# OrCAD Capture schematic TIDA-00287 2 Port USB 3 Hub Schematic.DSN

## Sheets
1 PAGE1_BLOCK_DIAGRAM: title: BLOCK DIAGRAM; rev: A
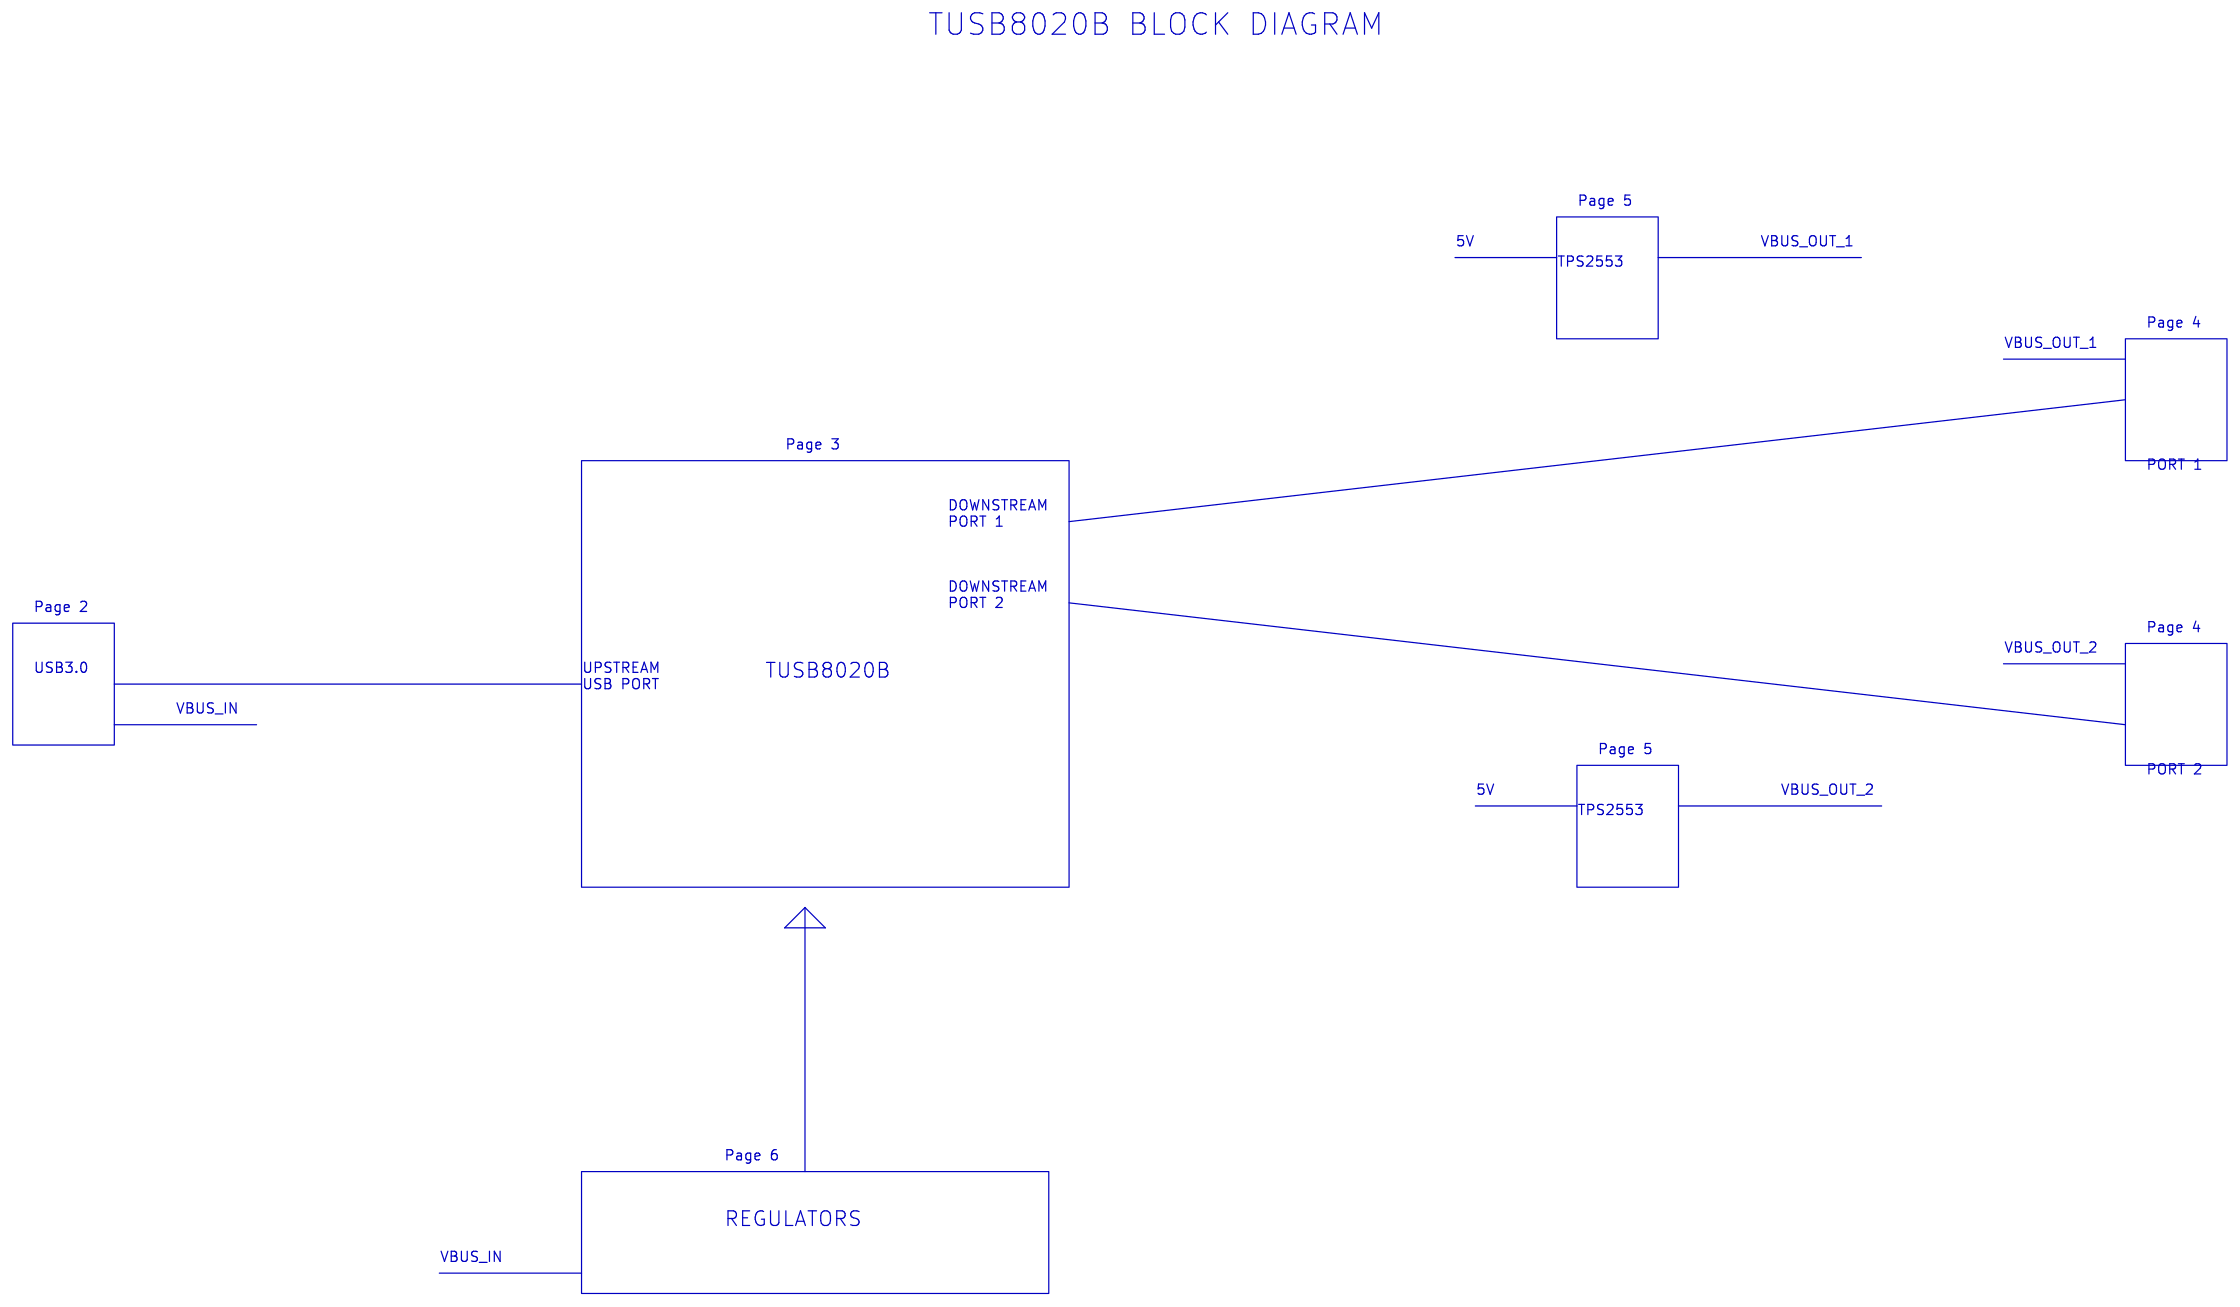
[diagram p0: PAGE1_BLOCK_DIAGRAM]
2 PAGE2_USB3_UPSTREAM_CONNECTOR: size B; title: USB 3.0 UPSTREAM CONNECTOR
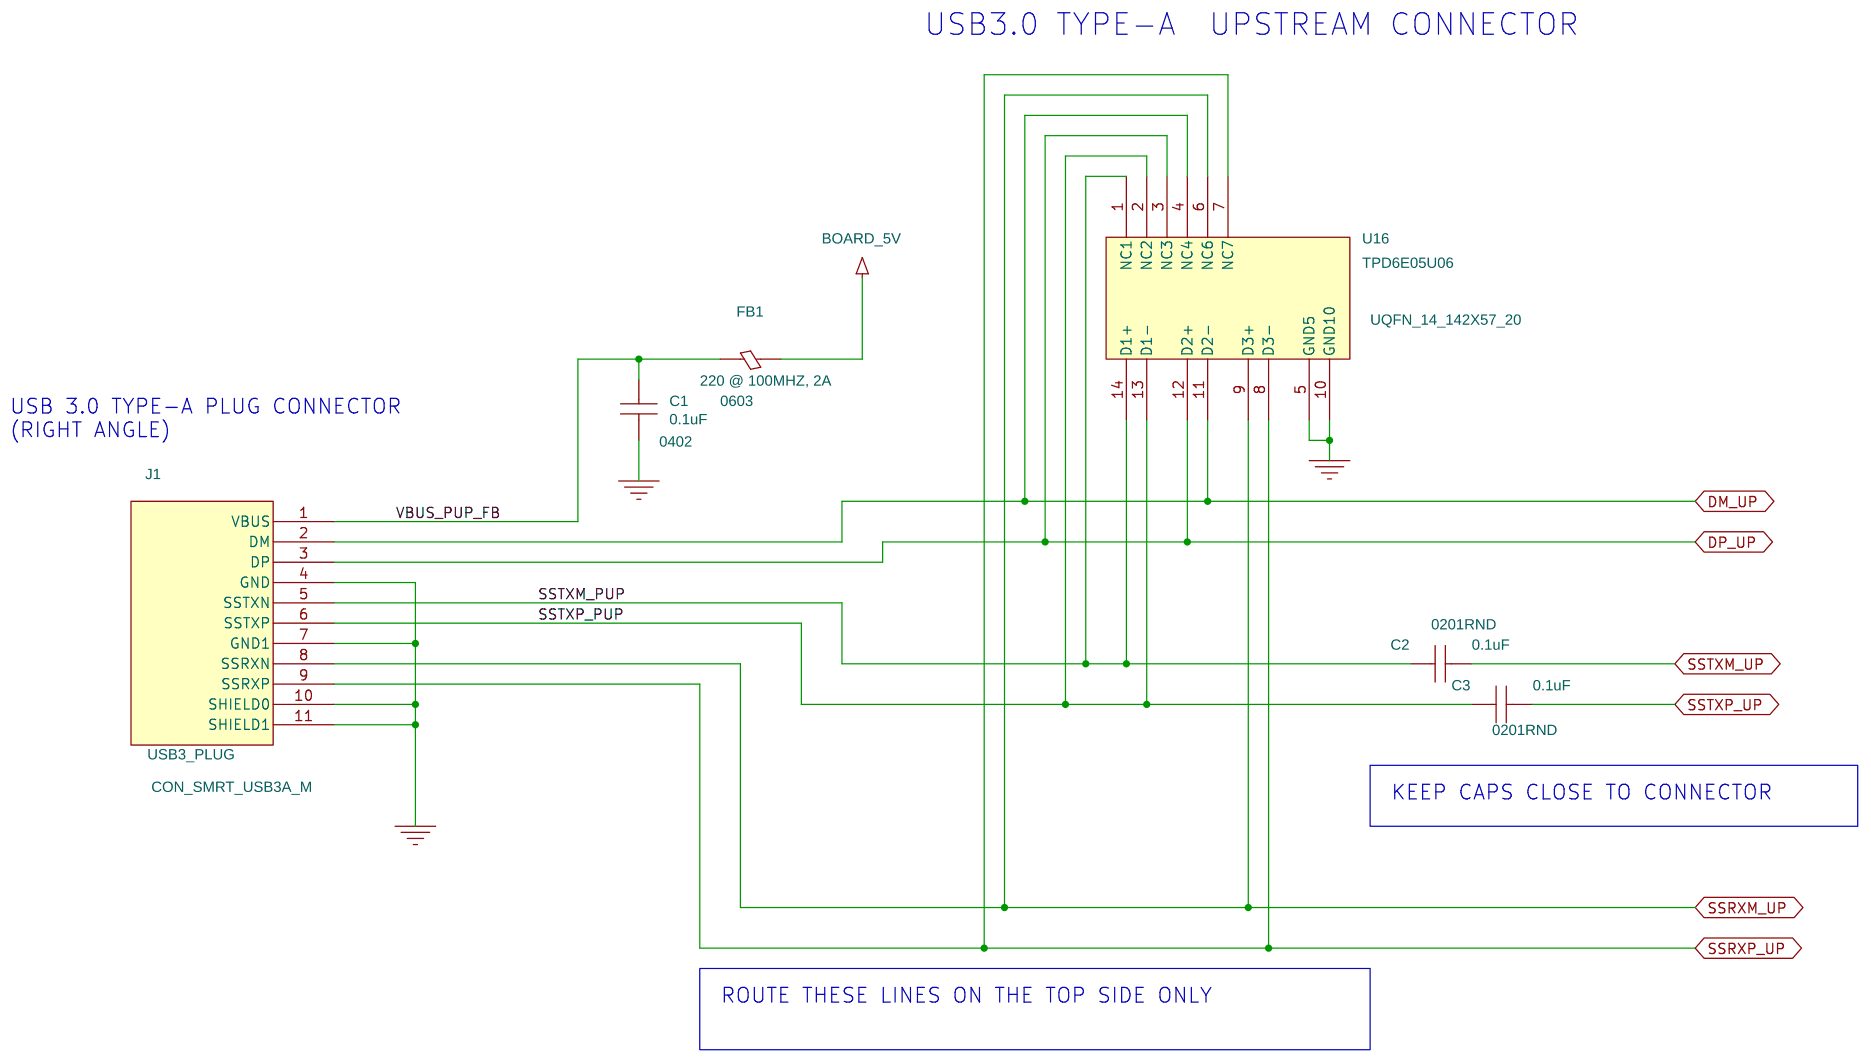
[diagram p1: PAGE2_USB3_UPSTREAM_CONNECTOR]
3 PAGE3_TUSB8020B: size B; title: TUSB8020B
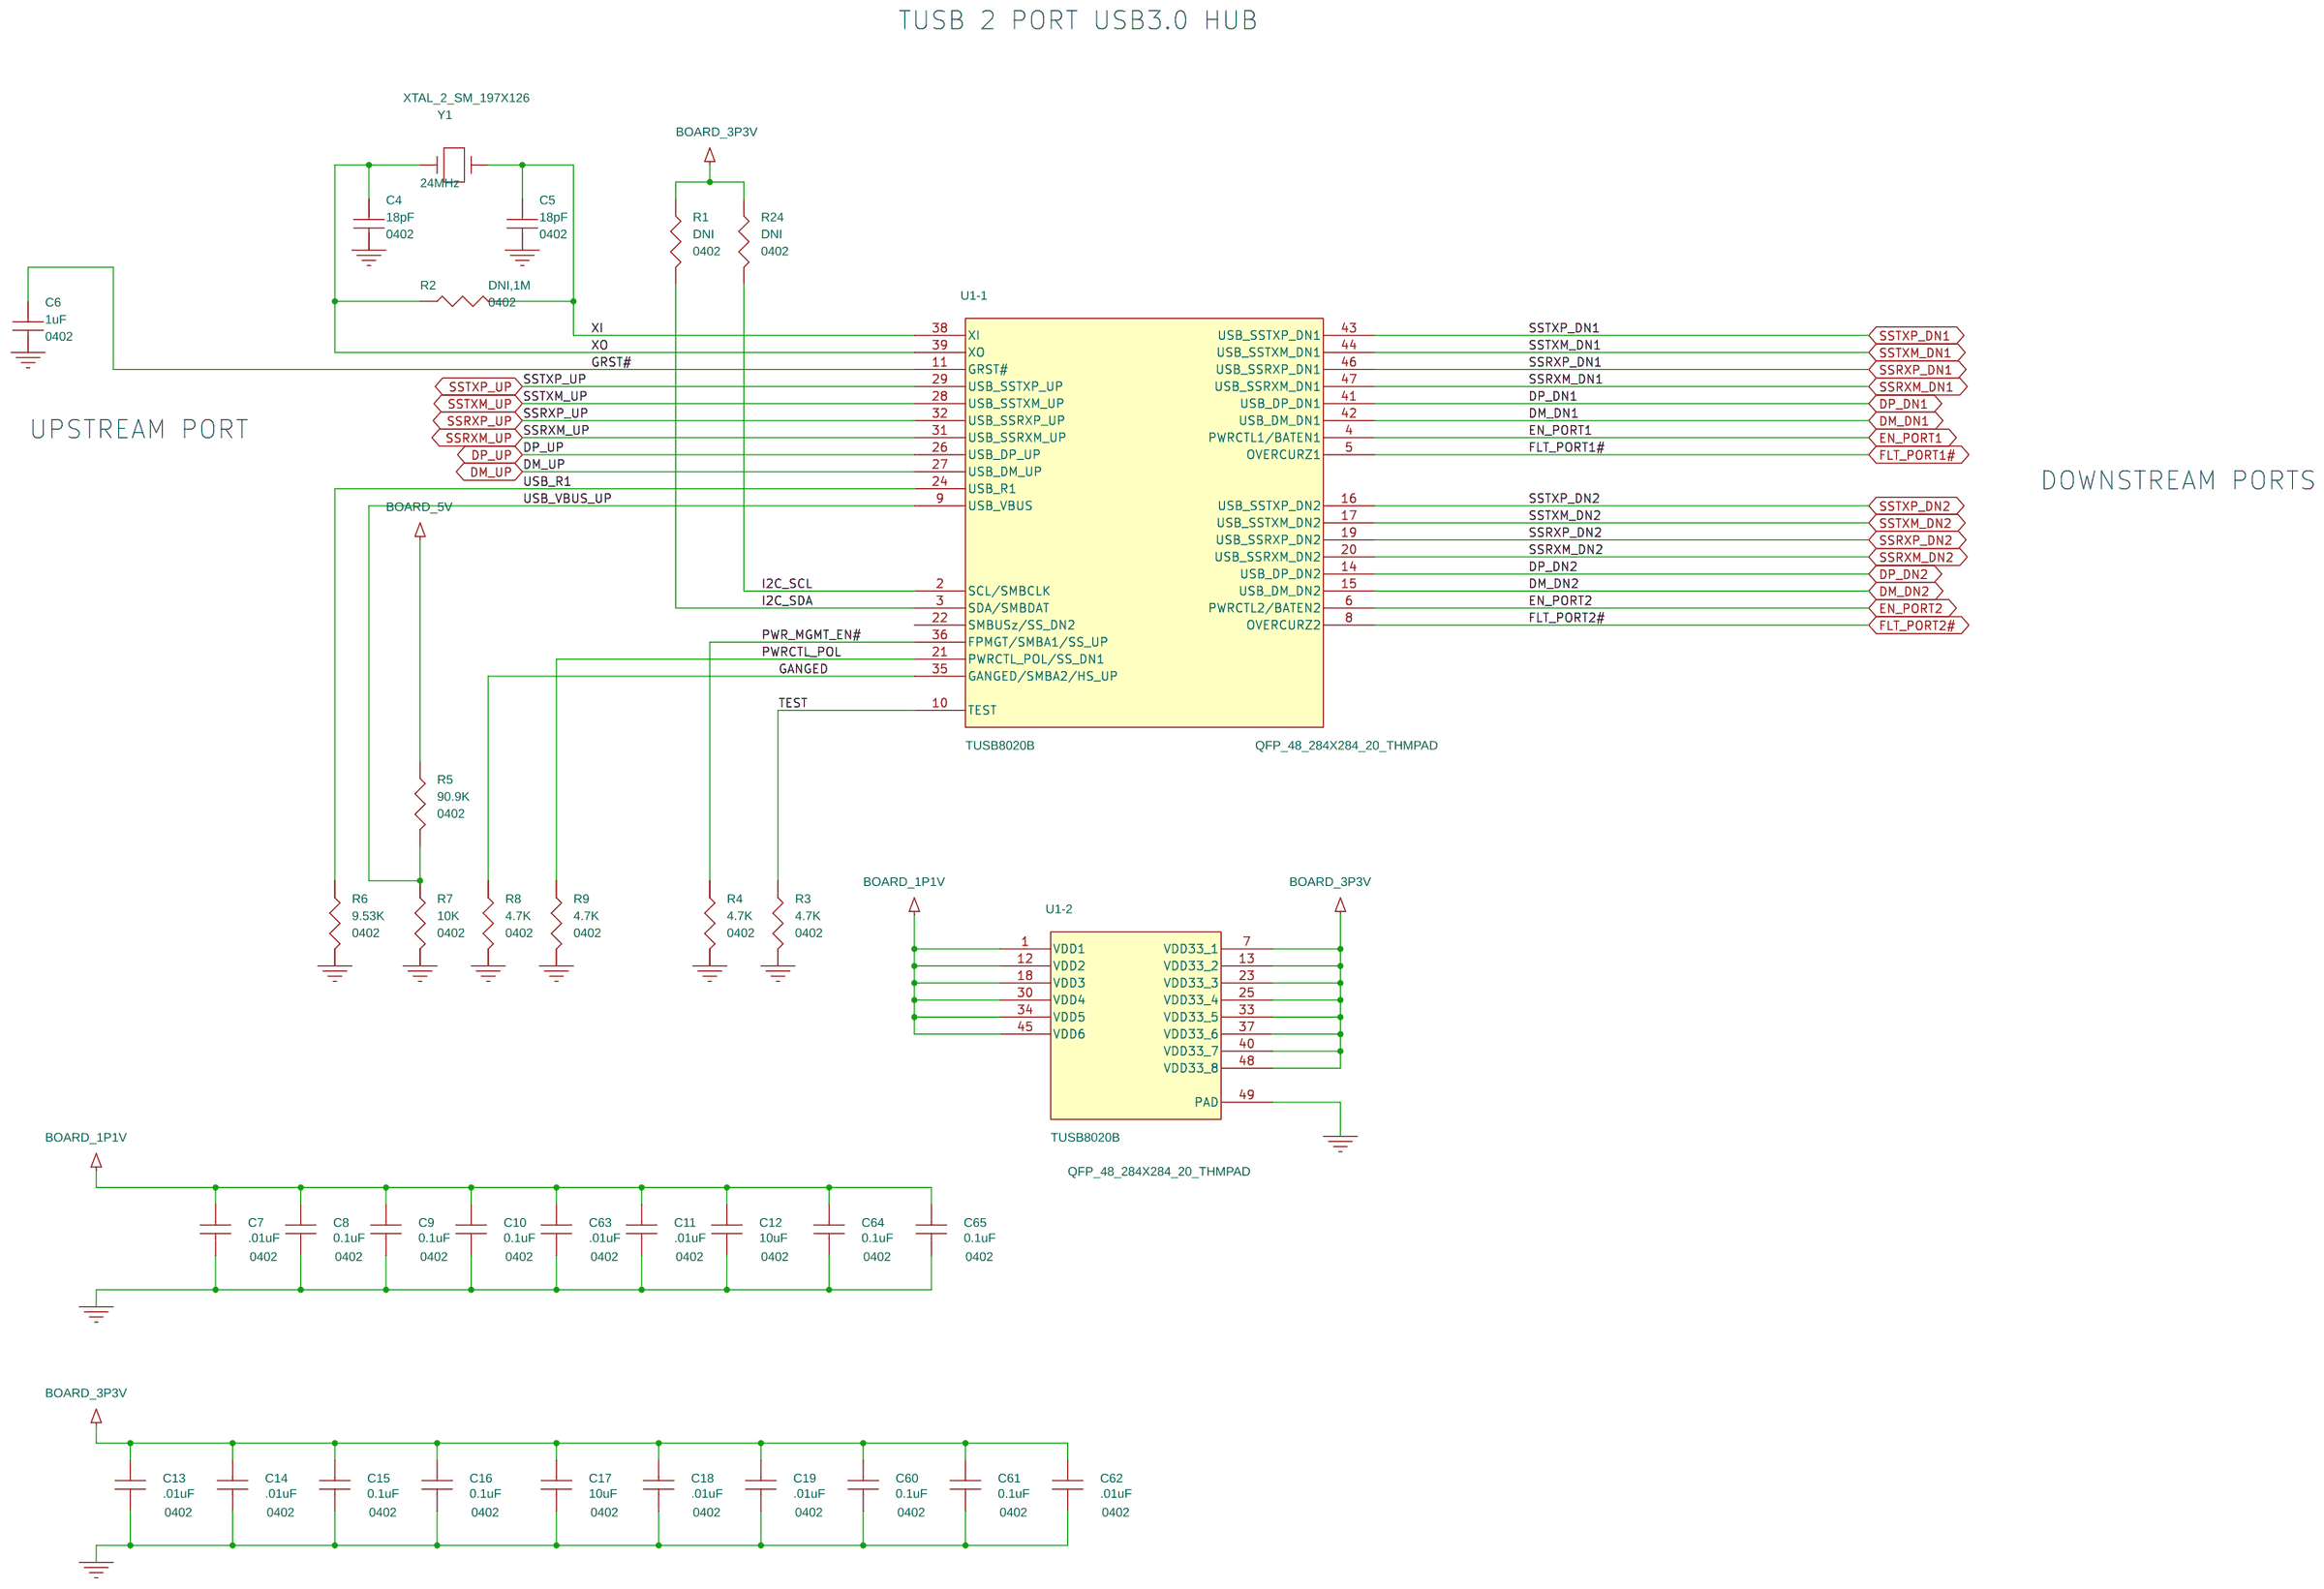
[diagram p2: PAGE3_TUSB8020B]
4 PAGE4_USB_DOWNSTREAM_PORTS_1_2: size B; title: USB DOWNSTREAM PORTS 1 AND 2; rev: B
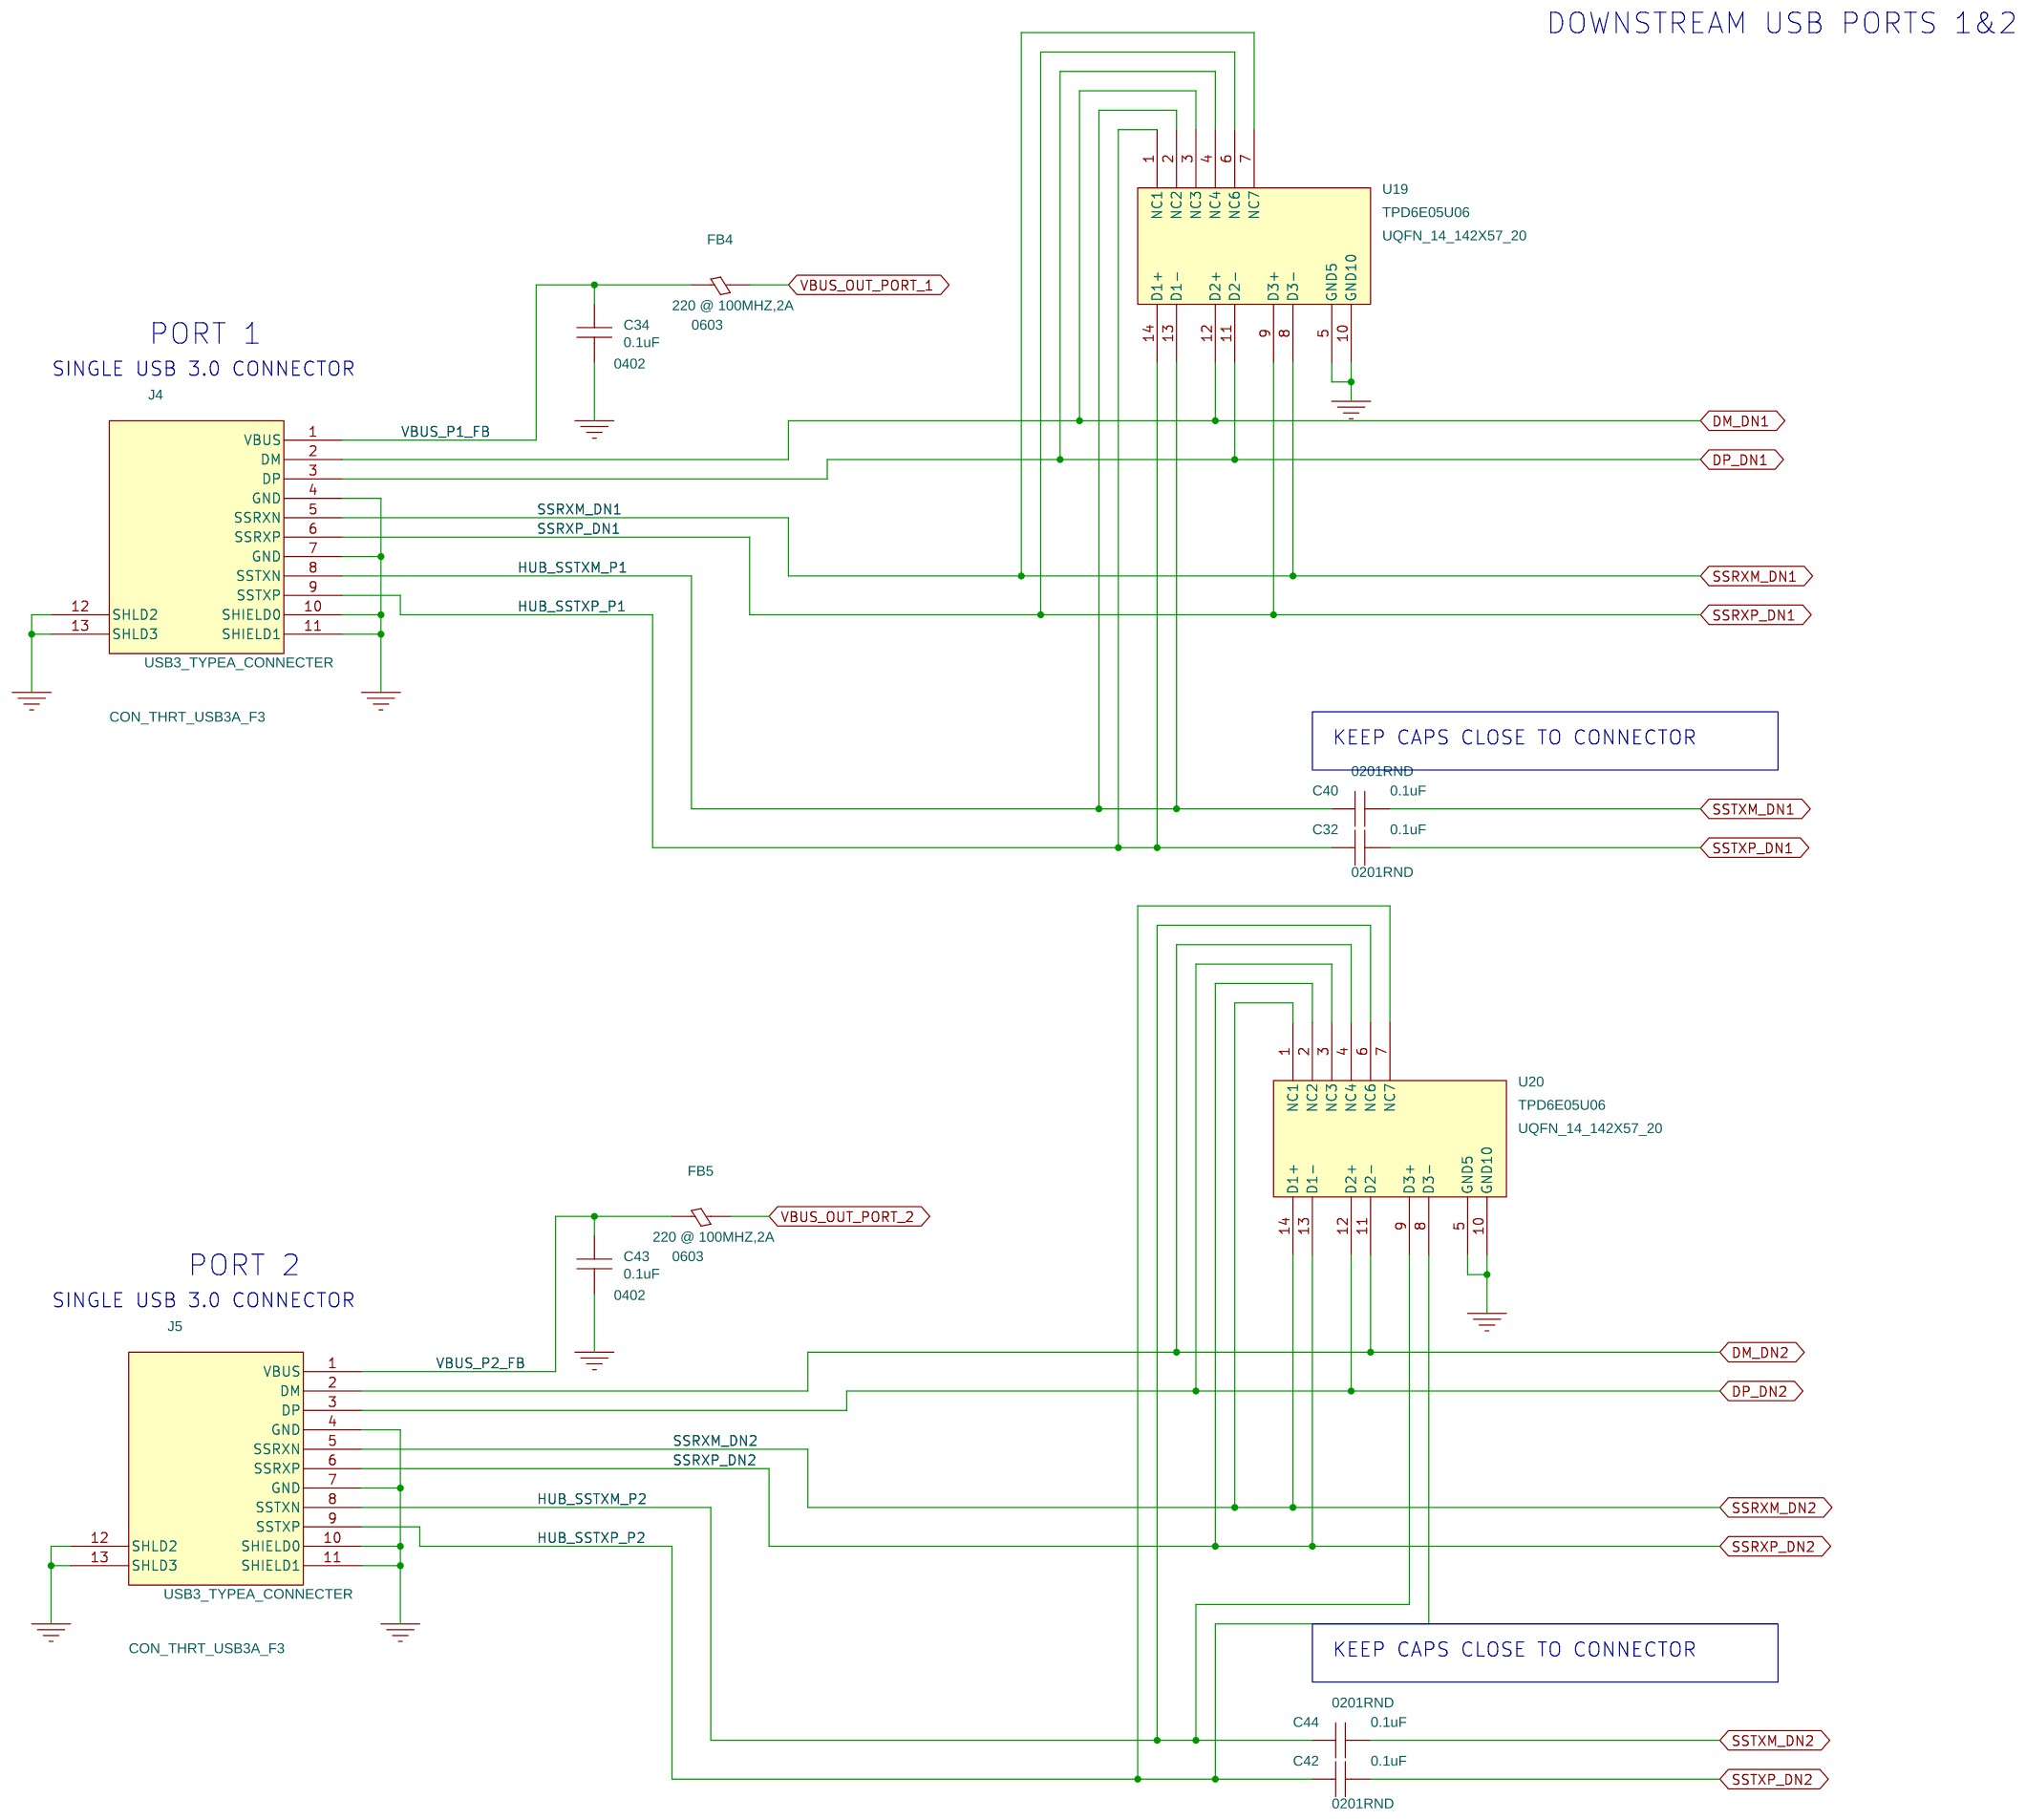
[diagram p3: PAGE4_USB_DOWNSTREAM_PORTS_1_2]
5 PAGE5_USB_POWER: size B; title: USB POWER
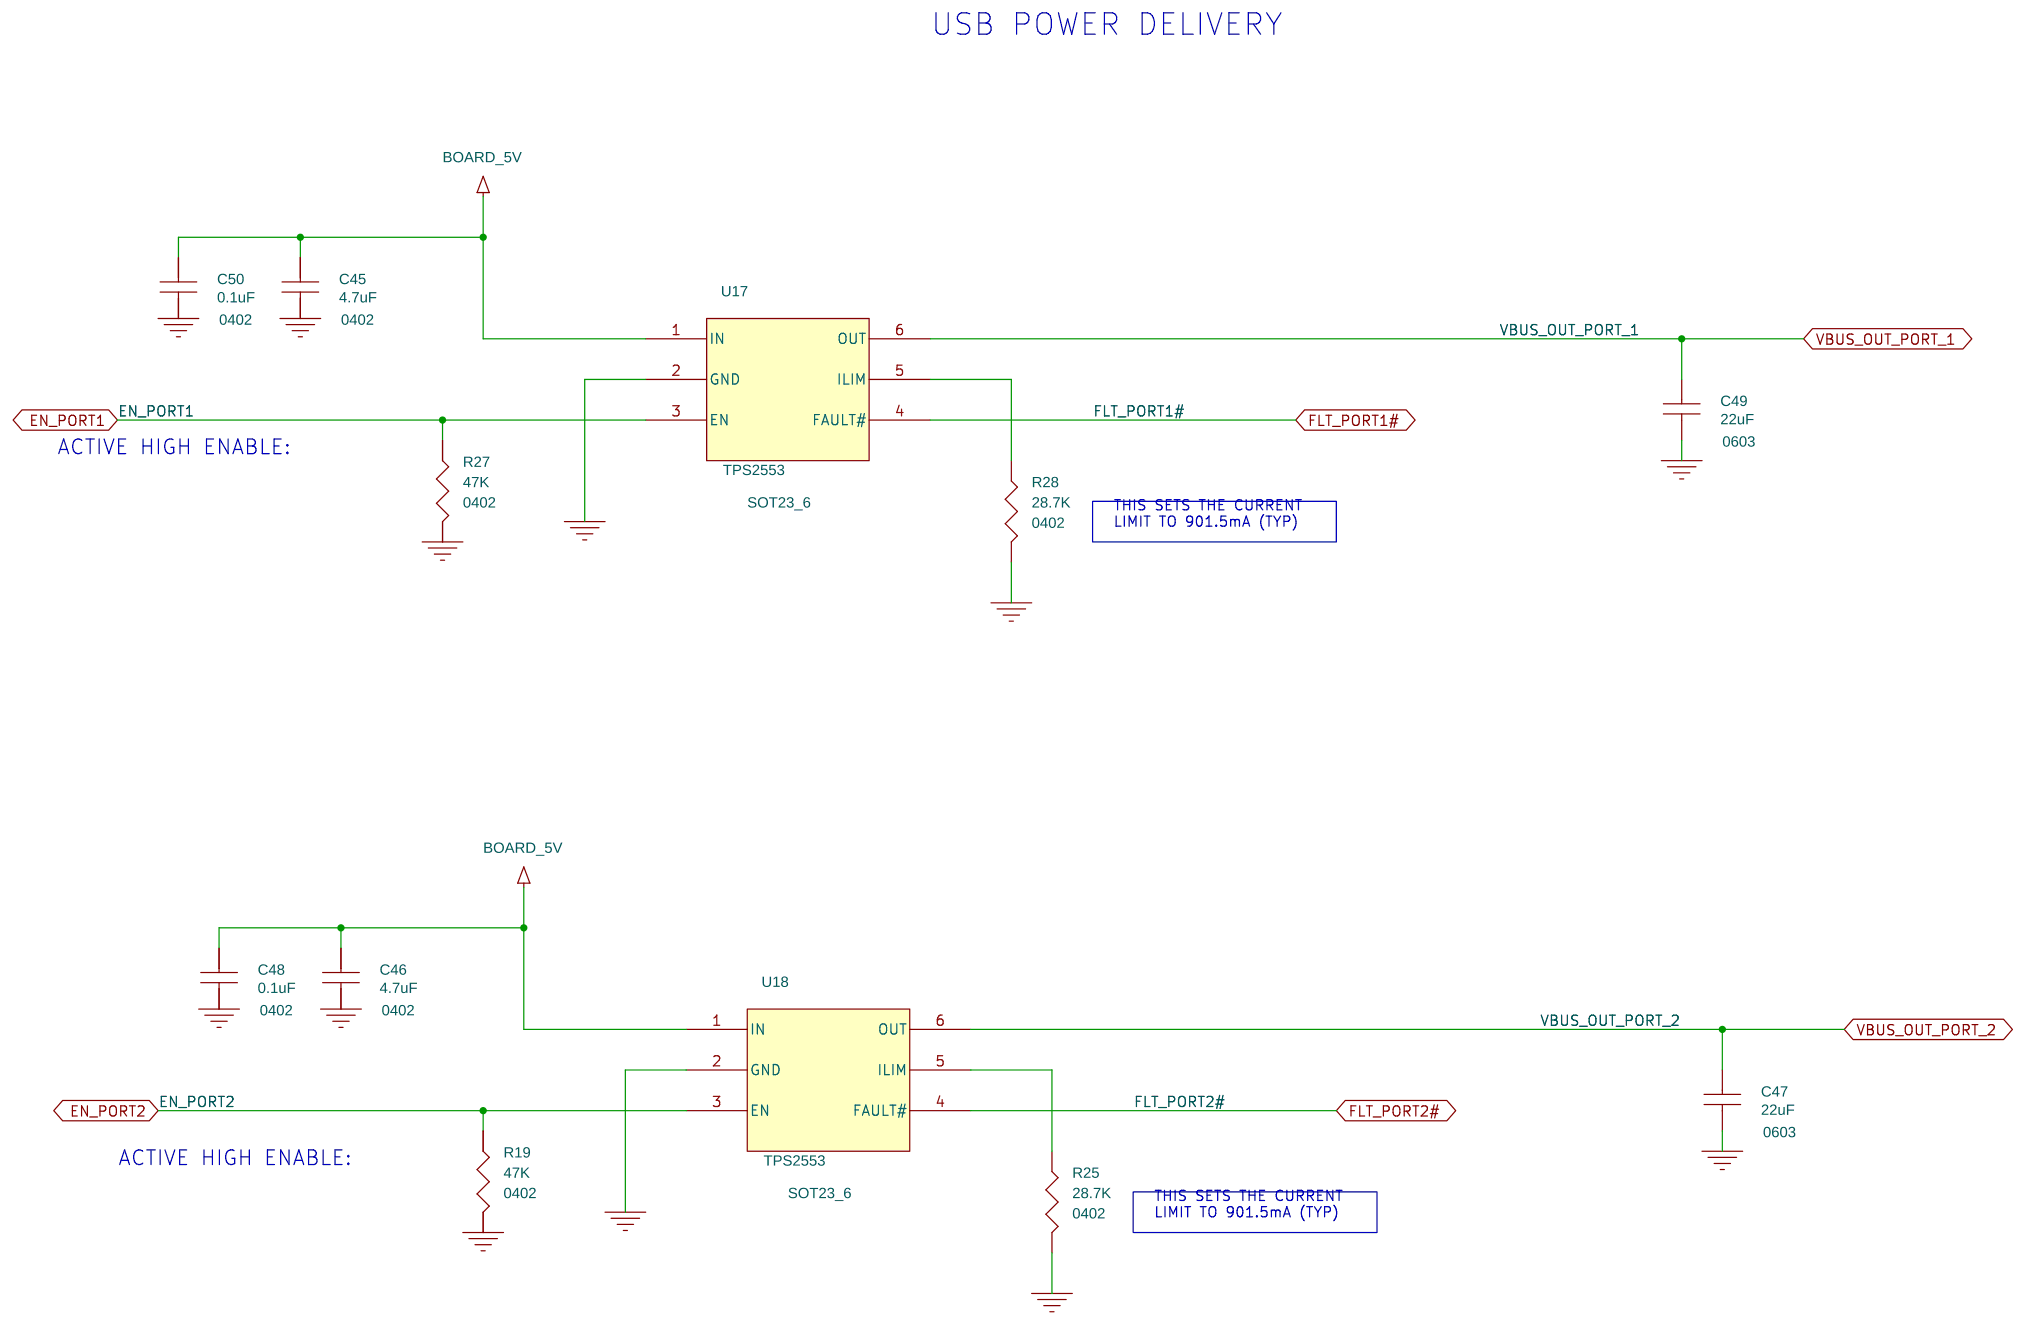
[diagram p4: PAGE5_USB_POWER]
6 PAGE6_POWER: size B; title: BOARD POWER
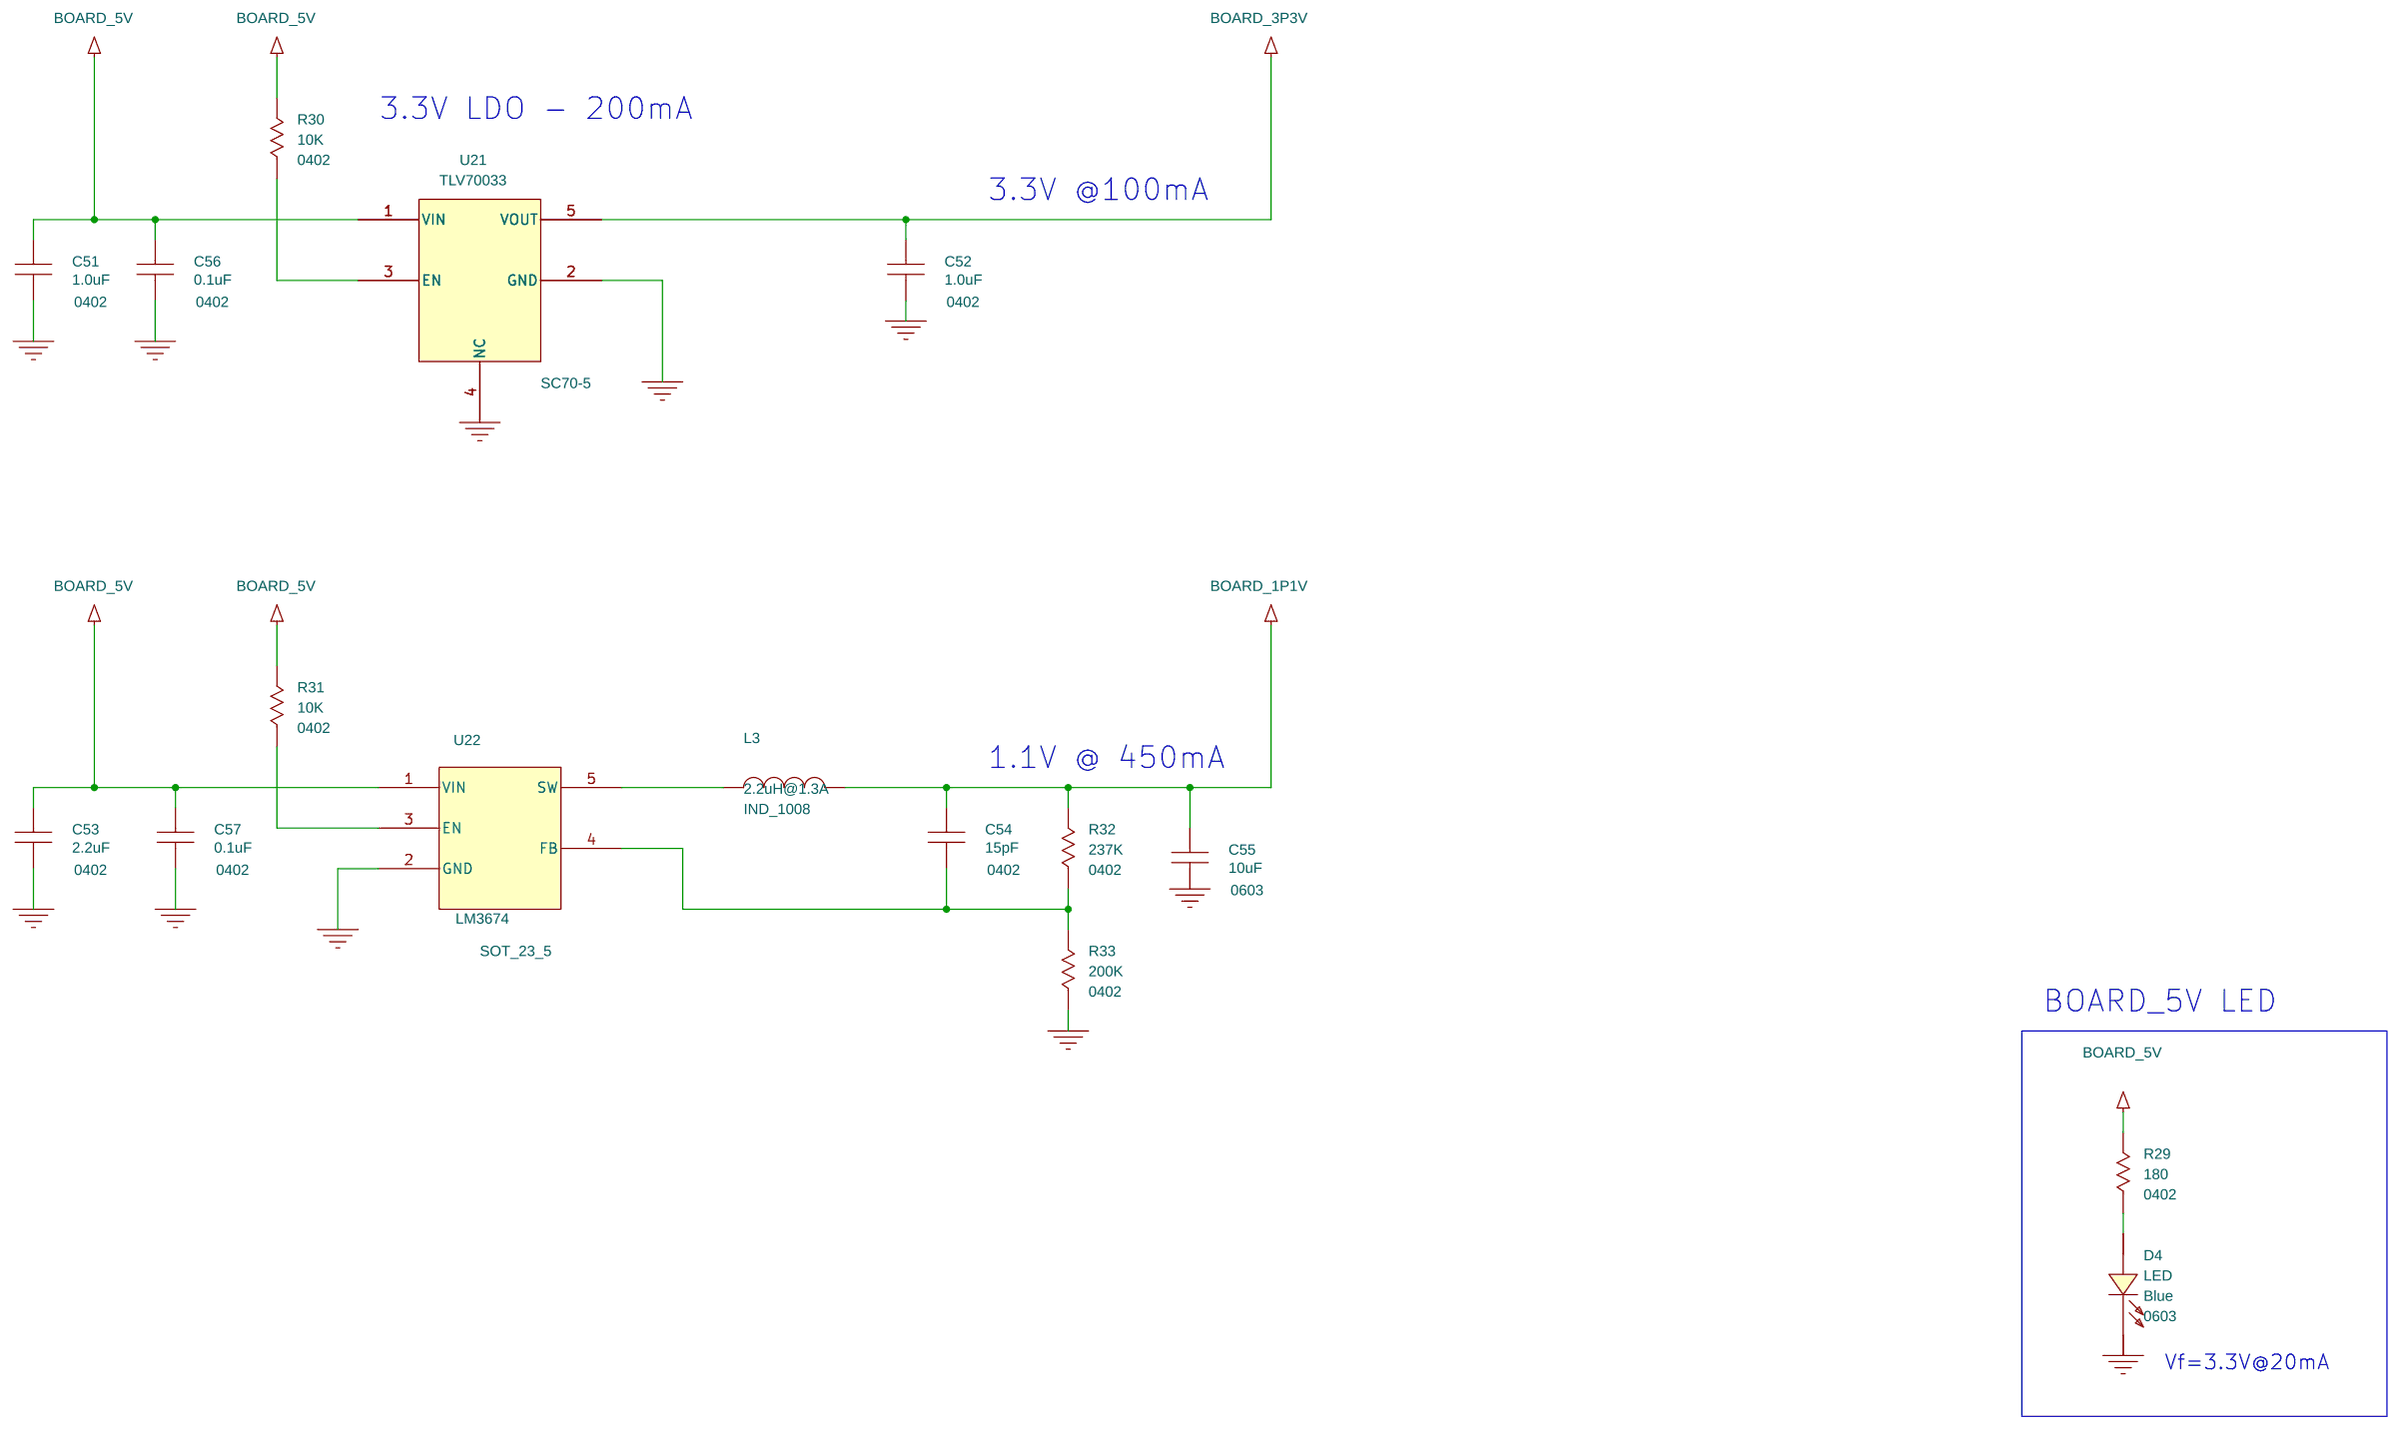
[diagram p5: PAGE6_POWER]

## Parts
sheet PAGE2_USB3_UPSTREAM_CONNECTOR
C1  0.1uF  [0402]
C2  0.1uF  [0201RND]
C3  0.1uF  [0201RND]
FB1  220 @ 100MHZ, 2A  [0603]
J1  USB3_PLUG  [CON_SMRT_USB3A_M]
U16  TPD6E05U06  [UQFN_14_142X57_20]
sheet PAGE3_TUSB8020B
C4  18pF  [0402]
C5  18pF  [0402]
C6  1uF  [0402]
C7  .01uF  [0402]
C8  0.1uF  [0402]
C9  0.1uF  [0402]
C10  0.1uF  [0402]
C11  .01uF  [0402]
C12  10uF  [0402]
C13  .01uF  [0402]
C14  .01uF  [0402]
C15  0.1uF  [0402]
C16  0.1uF  [0402]
C17  10uF  [0402]
C18  .01uF  [0402]
C19  .01uF  [0402]
C60  0.1uF  [0402]
C61  0.1uF  [0402]
C62  .01uF  [0402]
C63  .01uF  [0402]
C64  0.1uF  [0402]
C65  0.1uF  [0402]
R1  DNI  [0402]
R2  DNI,1M  [0402]
R3  4.7K  [0402]
R4  4.7K  [0402]
R5  90.9K  [0402]
R6  9.53K  [0402]
R7  10K  [0402]
R8  4.7K  [0402]
R9  4.7K  [0402]
R24  DNI  [0402]
U1  TUSB8020B  [QFP_48_284X284_20_THMPAD]  (sections -1,-2)
Y1  24MHz  [XTAL_2_SM_197X126]
sheet PAGE4_USB_DOWNSTREAM_PORTS_1_2
C32  0.1uF  [0201RND]
C34  0.1uF  [0402]
C40  0.1uF  [0201RND]
C42  0.1uF  [0201RND]
C43  0.1uF  [0402]
C44  0.1uF  [0201RND]
FB4  220 @ 100MHZ,2A  [0603]
FB5  220 @ 100MHZ,2A  [0603]
J4  USB3_TYPEA_CONNECTER  [CON_THRT_USB3A_F3]
J5  USB3_TYPEA_CONNECTER  [CON_THRT_USB3A_F3]
U19  TPD6E05U06  [UQFN_14_142X57_20]
U20  TPD6E05U06  [UQFN_14_142X57_20]
sheet PAGE5_USB_POWER
C45  4.7uF  [0402]
C46  4.7uF  [0402]
C47  22uF  [0603]
C48  0.1uF  [0402]
C49  22uF  [0603]
C50  0.1uF  [0402]
R19  47K  [0402]
R25  28.7K  [0402]
R27  47K  [0402]
R28  28.7K  [0402]
U17  TPS2553  [SOT23_6]
U18  TPS2553  [SOT23_6]
sheet PAGE6_POWER
C51  1.0uF  [0402]
C52  1.0uF  [0402]
C53  2.2uF  [0402]
C54  15pF  [0402]
C55  10uF  [0603]
C56  0.1uF  [0402]
C57  0.1uF  [0402]
D4  LED  [0603]
L3  2.2uH@1.3A  [IND_1008]
R29  180  [0402]
R30  10K  [0402]
R31  10K  [0402]
R32  237K  [0402]
R33  200K  [0402]
U21  TLV70033  [SC70-5]
U22  LM3674  [SOT_23_5]

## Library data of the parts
C1-C6 C32 C34 C40 C42-C44 = CAP_NP: 6.3V Capacitor
FB1 FB4 FB5 = FERRITE_BEAD: Ferrite Bead; Digi-Key Part Number: 490-3992-1-ND; Manufacturer: MuRata; Manufacturer's Part Number: BLM18EG221SN1D
J1 = USB3_PLUG: Manufacturer: Assmann; Manufacturer's Part Number: A-USB/3-A-LP/SMT-R
U16 U19 U20 = TPD6E05U06: MANUFACTURER: TEXAS INSTRUMENTS
C7-C19 C45-C57 C60-C65 = CAP_NP
R1 R3-R9 R19 R24 R25 R27 R28 = R
R2 = R: Resistor
U1 = TUSB8020B: MANUFACTURER: TEXAS INSTRUMENTS; Color: Default; Location X-Coordinate: 0; Location Y-Coordinate: 0; Package Type: Heterogeneous; Power Pins Visible: False; Primitive: DEFAULT; SPLIT_INST: TRUE; SWAP_INFO: (S1+S2)
Y1 = CRYSTAL: Crystal; Manufacturer: CTS Freq Controls; Manufacturer's Part Number: 445C25D24M00000
J4 J5 = USB3_TYPEA_CONNECTER
U17 U18 = TPS2553: MANUFACTURER: TEXAS INSTRUMENTS
D4 = LED: LED Color: Blue; Manufacturer: Lite-On Inc.; Manufacturer's Part Number: LTST-C170TBK
L3 = INDUCTOR: Manufacturer: Murata; Manufacturer's Part Number: LQM2HPN2R2MG0L
R29-R33 = R_v2
U21 = TLV70033: MANUFACTURER: TEXAS INSTRUMENTS
U22 = LM3674: MANUFACTURER: TEXAS INSTRUMENTS

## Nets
GND: C1.2 C4.2 C5.2 C6.2 C7.2 C8.2 C9.2 C10.2 C11.2 C12.2 C13.2 C14.2 C15.2 C16.2 C17.2 C18.2 C19.2 C34.2 C43.2 C45.2 C46.2 C47.2 C48.2 C49.2 C50.2 C51.2 C52.2 C53.2 C55.2 C56.2 C57.2 C60.2 C61.2 C62.2 C63.2 C64.2 C65.2 D4.1(CATHODE) J1.4(GND) J1.7(GND1) J1.10(SHIELD0) J1.11(SHIELD1) J4.4(GND) J4.7(GND) J4.10(SHIELD0) J4.11(SHIELD1) J4.12(SHLD2) J4.13(SHLD3) J5.4(GND) J5.7(GND) J5.10(SHIELD0) J5.11(SHIELD1) J5.12(SHLD2) J5.13(SHLD3) R3.2 R4.2 R6.2 R7.2 R8.2 R9.2 R19.2 R25.2 R27.2 R28.2 R33.2 U1.49(PAD) U16.5(GND5) U16.10(GND10) U17.2(GND) U18.2(GND) U19.5(GND5) U19.10(GND10) U20.5(GND5) U20.10(GND10) U21.2(GND) U21.4(NC) U22.2(GND)
VBUS_OUT_PORT_1: C49.1 FB4.2 U17.6(OUT)
VBUS_OUT_PORT_2: C47.1 FB5.2 U18.6(OUT)
VBUS_P1_FB: C34.1 FB4.1 J4.1(VBUS)
VBUS_P2_FB: C43.1 FB5.1 J5.1(VBUS)
VBUS_PUP_FB: C1.1 FB1.1 J1.1(VBUS)
BOARD_1P1V: C7.1 C8.1 C9.1 C10.1 C11.1 C12.1 C54.1 C55.1 C63.1 C64.1 C65.1 L3.2 R32.1 U1.1(VDD1) U1.12(VDD2) U1.18(VDD3) U1.30(VDD4) U1.34(VDD5) U1.45(VDD6)
BOARD_3P3V: C13.1 C14.1 C15.1 C16.1 C17.1 C18.1 C19.1 C52.1 C60.1 C61.1 C62.1 R1.1 R24.1 U1.7(VDD33_1) U1.13(VDD33_2) U1.23(VDD33_3) U1.25(VDD33_4) U1.33(VDD33_5) U1.37(VDD33_6) U1.40(VDD33_7) U1.48(VDD33_8) U21.5(VOUT)
BOARD_5V: C45.1 C46.1 C48.1 C50.1 C51.1 C53.1 C56.1 C57.1 FB1.2 R5.1 R29.1 R30.1 R31.1 U17.1(IN) U18.1(IN) U21.1(VIN) U22.1(VIN)
DM_DN1: J4.2(DM) U1.42(USB_DM_DN1) U19.3(NC3) U19.12(D2+)
DM_DN2: J5.2(DM) U1.15(USB_DM_DN2) U20.4(NC4) U20.11(D2-)
DM_UP: J1.2(DM) U1.27(USB_DM_UP) U16.4(NC4) U16.11(D2-)
DP_DN1: J4.3(DP) U1.41(USB_DP_DN1) U19.4(NC4) U19.11(D2-)
DP_DN2: J5.3(DP) U1.14(USB_DP_DN2) U20.3(NC3) U20.12(D2+)
DP_UP: J1.3(DP) U1.26(USB_DP_UP) U16.3(NC3) U16.12(D2+)
EN_PORT1: R27.1 U1.4(PWRCTL1/BATEN1) U17.3(EN)
EN_PORT2: R19.1 U1.6(PWRCTL2/BATEN2) U18.3(EN)
FLT_PORT1#: U1.5(OVERCURZ1) U17.4(FAULT#)
FLT_PORT2#: U1.8(OVERCURZ2) U18.4(FAULT#)
GANGED: R8.1 U1.35(GANGED/SMBA2/HS_UP)
GRST#: C6.1 U1.11(GRST#)
HUB_SSTXM_P1: C40.1 J4.8(SSTXN) U19.2(NC2) U19.13(D1-)
HUB_SSTXM_P2: C44.1 J5.8(SSTXN) U20.6(NC6) U20.9(D3+)
HUB_SSTXP_P1: C32.1 J4.9(SSTXP) U19.1(NC1) U19.14(D1+)
HUB_SSTXP_P2: C42.1 J5.9(SSTXP) U20.7(NC7) U20.8(D3-)
I2C_SCL: R24.2 U1.2(SCL/SMBCLK)
I2C_SDA: R1.2 U1.3(SDA/SMBDAT)
PWR_MGMT_EN#: R4.1 U1.36(FPMGT/SMBA1/SS_UP)
PWRCTL_POL: R9.1 U1.21(PWRCTL_POL/SS_DN1)
SSRXM_DN1: J4.5(SSRXN) U1.47(USB_SSRXM_DN1) U19.7(NC7) U19.8(D3-)
SSRXM_DN2: J5.5(SSRXN) U1.20(USB_SSRXM_DN2) U20.1(NC1) U20.14(D1+)
SSRXM_UP: J1.8(SSRXN) U1.31(USB_SSRXM_UP) U16.6(NC6) U16.9(D3+)
SSRXP_DN1: J4.6(SSRXP) U1.46(USB_SSRXP_DN1) U19.6(NC6) U19.9(D3+)
SSRXP_DN2: J5.6(SSRXP) U1.19(USB_SSRXP_DN2) U20.2(NC2) U20.13(D1-)
SSRXP_UP: J1.9(SSRXP) U1.32(USB_SSRXP_UP) U16.7(NC7) U16.8(D3-)
SSTXM_DN1: C40.2 U1.44(USB_SSTXM_DN1)
SSTXM_DN2: C44.2 U1.17(USB_SSTXM_DN2)
SSTXM_PUP: C2.1 J1.5(SSTXN) U16.1(NC1) U16.14(D1+)
SSTXM_UP: C2.2 U1.28(USB_SSTXM_UP)
SSTXP_DN1: C32.2 U1.43(USB_SSTXP_DN1)
SSTXP_DN2: C42.2 U1.16(USB_SSTXP_DN2)
SSTXP_PUP: C3.1 J1.6(SSTXP) U16.2(NC2) U16.13(D1-)
SSTXP_UP: C3.2 U1.29(USB_SSTXP_UP)
TEST: R3.1 U1.10(TEST)
USB_R1: R6.1 U1.24(USB_R1)
USB_VBUS_UP: R5.2 R7.1 U1.9(USB_VBUS)
XI: C5.1 R2.2 U1.38(XI) Y1.2
XO: C4.1 R2.1 U1.39(XO) Y1.1
N16828952: R28.1 U17.5(ILIM)
N16829037: R25.1 U18.5(ILIM)
N16829593: D4.2(ANODE) R29.2
N16829632: R30.2 U21.3(EN)
N16829759: R31.2 U22.3(EN)
N16829814: C54.2 R32.2 R33.1 U22.4(FB)
N16829841: L3.1 U22.5(SW)

Not connected (* = marked no-connect by the designer): U1 22(SMBUSz/SS_DN2)

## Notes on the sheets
sheet 1
- TUSB8020B BLOCK DIAGRAM
- Page 5
- 5V
- VBUS_OUT_1
- TPS2553
- Page 4
- VBUS_OUT_1
- Page 3
- PORT 1
- DOWNSTREAM
  PORT 1
- DOWNSTREAM
  PORT 2
- Page 2
- Page 4
- VBUS_OUT_2
- USB3.0
- UPSTREAM
  USB PORT
- TUSB8020B
- VBUS_IN
- Page 5
- PORT 2
- 5V
- VBUS_OUT_2
- TPS2553
- Page 6
- REGULATORS
- VBUS_IN
sheet 2
- USB3.0 TYPE-A  UPSTREAM CONNECTOR
- USB 3.0 TYPE-A PLUG CONNECTOR
  (RIGHT ANGLE)
- KEEP CAPS CLOSE TO CONNECTOR
- ROUTE THESE LINES ON THE TOP SIDE ONLY
sheet 3
- TUSB 2 PORT USB3.0 HUB
- UPSTREAM PORT
- DOWNSTREAM PORTS
sheet 4
- DOWNSTREAM USB PORTS 1&2
- PORT 1
- SINGLE USB 3.0 CONNECTOR
- KEEP CAPS CLOSE TO CONNECTOR
- PORT 2
- SINGLE USB 3.0 CONNECTOR
- KEEP CAPS CLOSE TO CONNECTOR
sheet 5
- USB POWER DELIVERY
- ACTIVE HIGH ENABLE:
- THIS SETS THE CURRENT
  LIMIT TO 901.5mA (TYP)
- ACTIVE HIGH ENABLE:
- THIS SETS THE CURRENT
  LIMIT TO 901.5mA (TYP)
sheet 6
- 3.3V LDO - 200mA
- 3.3V @100mA
- 1.1V @ 450mA
- BOARD_5V LED
- Vf=3.3V@20mA
